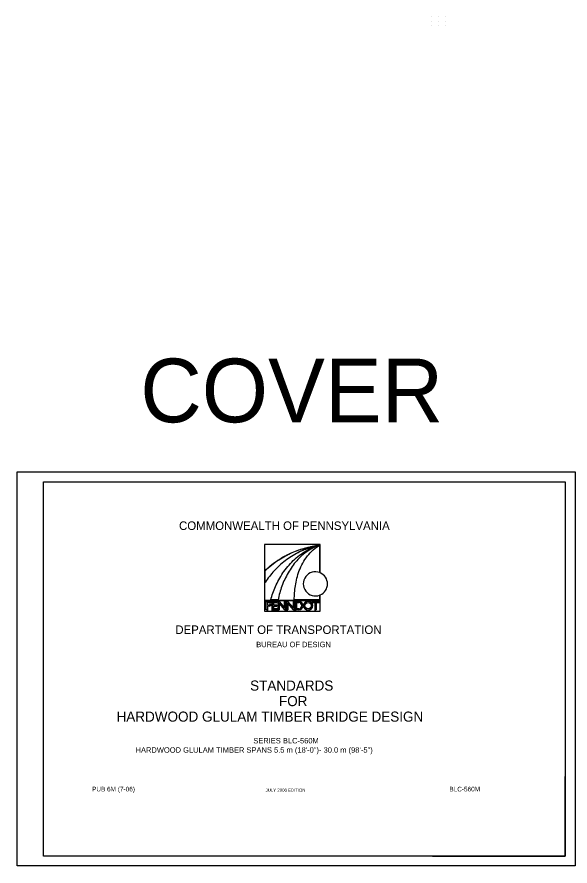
# Model space of a CAD drawing. Extents: x 637594 to 640253, y 297247 to 298527.
# Drawn here: x 637594 to 638428, y 297247 to 298527 of the extents above; entities that cross this region are included whole.
import ezdxf

# ---------------------------------------------------------------- set-up
doc = ezdxf.new("R2010")
doc.units = 0
for name, color, linetype in [('2', 7, 'Continuous'), ('4', 7, 'Continuous'), ('62', 7, 'Continuous'), ('9', 7, 'Continuous'), ('PLT-BNDY', 7, 'Continuous')]:
    doc.layers.add(name, color=color, linetype=linetype)

msp = doc.modelspace()

# ---------------------------------------------------------------- linework, layer by layer
at = {"layer": '2'}
for p, q in [((637634.5, 297262.5), (637634.5, 297826.5)), ((637634.5, 297826.5), (638420.5, 297826.5)), ((638420.5, 297826.5), (638420.5, 297262.5)), ((638420.5, 297262.5), (638420.5, 297382.5)), ((638420.5, 297262.5), (637634.5, 297262.5)), ((638220.5, 297262.5), (638420.5, 297262.5))]:
    msp.add_line(p, q, dxfattribs=at)
at = {"layer": '62'}
for p, q in [((638219.4, 298527.5), (638219.4, 298527.5)), ((638219.4, 298520.8), (638219.4, 298520.8)), ((638229.8, 298527.5), (638229.8, 298527.5)), ((638229.8, 298520.8), (638229.8, 298520.8)), ((638240.2, 298527.5), (638240.2, 298527.5)), ((638240.2, 298520.8), (638240.2, 298520.8)), ((638219.4, 298514.1), (638219.4, 298514.1)), ((638229.8, 298514.1), (638229.8, 298514.1)), ((638240.2, 298514.1), (638240.2, 298514.1))]:
    msp.add_line(p, q, dxfattribs=at)
at = {"layer": '9'}
for p, q in [((638051.6, 297732.1), (637967.3, 297732.1)), ((637967.3, 297732.1), (637967.3, 297647.9)), ((638051.6, 297732.1), (637967.3, 297732.1)), ((637967.3, 297732.1), (637967.3, 297674.9)), ((638051.6, 297732.1), (638050.6, 297731.1)), ((638050.6, 297731.1), (638051.6, 297732.1)), ((638051.6, 297732.1), (638050.6, 297731.1)), ((638050.6, 297731.1), (638050.6, 297689.8)), ((638050.6, 297731.1), (638050.6, 297689.8)), ((638051.6, 297689.4), (638051.6, 297732.1)), ((638051.6, 297689.4), (638051.6, 297732.1)), ((637967.3, 297674.9), (637968.3, 297674.9)), ((637967.3, 297674.9), (637968.3, 297674.9)), ((637968.3, 297674.9), (637967.3, 297674.9)), ((637967.3, 297674.9), (637967.3, 297647.9)), ((638051.6, 297647.9), (637967.3, 297647.9)), ((637967.3, 297647.9), (637967.3, 297631.9)), ((637974.3, 297647.9), (637967.3, 297647.9)), ((637967.3, 297647.9), (637967.3, 297631.9)), ((637967.3, 297647.9), (637976.9, 297647.9)), ((637970.1, 297633.7), (637970.1, 297646.4)), ((637970.1, 297646.4), (637974.3, 297646.4)), ((637970.1, 297633.7), (637970.1, 297646.4)), ((637970.1, 297646.4), (637974.3, 297646.4)), ((637974.3, 297647.9), (637974.3, 297646.4)), ((637974.3, 297646.4), (637974.3, 297647.9)), ((637986.3, 297647.9), (637974.3, 297647.9)), ((637974.3, 297647.9), (637974.3, 297646.4)), ((637976.9, 297647.9), (637976.9, 297648.9)), ((637976.9, 297647.9), (637976.9, 297648.9)), ((637976.9, 297648.9), (637976.9, 297647.9)), ((637976.9, 297647.9), (638012.4, 297647.9)), ((637979.3, 297646.4), (637979.3, 297633.7)), ((637986.3, 297646.4), (637979.3, 297646.4)), ((637979.3, 297633.7), (637979.3, 297646.4)), ((637979.3, 297646.4), (637986.3, 297646.4)), ((637986.3, 297647.9), (637986.3, 297646.4)), ((637986.3, 297646.4), (637986.3, 297647.9)), ((637999.5, 297647.9), (637986.3, 297647.9)), ((637986.3, 297647.9), (637986.3, 297646.4)), ((637986.3, 297644.7), (637986.3, 297646.4)), ((637986.3, 297646.4), (637986.3, 297644.7)), ((637989.5, 297646.4), (637988.1, 297646.4)), ((637988.1, 297646.4), (637988.1, 297633.7)), ((637988.1, 297633.7), (637988.1, 297646.4)), ((637988.1, 297646.4), (637989.5, 297646.4)), ((637997.8, 297636.6), (637989.5, 297646.4)), ((637989.5, 297646.4), (637997.8, 297636.6)), ((637999.5, 297646.4), (637997.8, 297646.4)), ((637997.8, 297646.4), (637997.8, 297636.6)), ((637997.8, 297636.6), (637997.8, 297646.4)), ((637997.8, 297646.4), (637999.5, 297646.4)), ((637999.5, 297647.9), (637999.5, 297646.4)), ((637999.5, 297646.4), (637999.5, 297647.9)), ((638012.7, 297647.9), (637999.5, 297647.9)), ((637999.5, 297647.9), (637999.5, 297646.4)), ((637999.5, 297633.7), (637999.5, 297646.4)), ((637999.5, 297646.4), (637999.5, 297633.7)), ((638002.7, 297646.4), (638001.2, 297646.4)), ((638001.2, 297646.4), (638001.2, 297633.7)), ((638001.2, 297633.7), (638001.2, 297646.4)), ((638001.2, 297646.4), (638002.7, 297646.4)), ((638011, 297636.6), (638002.7, 297646.4)), ((638002.7, 297646.4), (638011, 297636.6)), ((638012.7, 297646.4), (638011, 297646.4)), ((638011, 297646.4), (638011, 297636.6)), ((638011, 297636.6), (638011, 297646.4)), ((638011, 297646.4), (638012.7, 297646.4)), ((638050.6, 297648.9), (638012.4, 297648.9)), ((638012.4, 297647.9), (638012.4, 297648.9)), ((638012.4, 297647.9), (638012.4, 297648.9)), ((638050.6, 297648.9), (638012.4, 297648.9)), ((638012.4, 297648.9), (638012.4, 297647.9)), ((638012.4, 297647.9), (638051.6, 297647.9)), ((638012.7, 297647.9), (638012.7, 297646.4)), ((638012.7, 297646.4), (638012.7, 297647.9)), ((638019.4, 297647.9), (638012.7, 297647.9)), ((638012.7, 297647.9), (638012.7, 297646.4)), ((638012.7, 297633.7), (638012.7, 297646.4)), ((638012.7, 297646.4), (638012.7, 297633.7)), ((638014.4, 297633.7), (638014.4, 297646.4)), ((638014.4, 297646.4), (638019.4, 297646.4)), ((638014.4, 297633.7), (638014.4, 297646.4)), ((638014.4, 297646.4), (638019.4, 297646.4)), ((638014.4, 297633.7), (638014.4, 297646.4)), ((638014.4, 297646.4), (638019.4, 297646.4)), ((638019.4, 297647.9), (638019.4, 297646.4)), ((638019.4, 297646.4), (638019.4, 297647.9)), ((638033.3, 297647.9), (638019.4, 297647.9)), ((638019.4, 297647.9), (638019.4, 297646.4)), ((638033.3, 297647.9), (638033.3, 297646.6)), ((638033.3, 297646.6), (638033.3, 297647.9)), ((638050, 297647.9), (638033.3, 297647.9)), ((638033.3, 297647.9), (638033.3, 297646.6)), ((638050, 297646.4), (638039.6, 297646.4)), ((638039.6, 297646.4), (638039.6, 297644.7)), ((638050, 297646.4), (638039.6, 297646.4)), ((638039.6, 297646.4), (638050, 297646.4)), ((638039.6, 297644.7), (638039.6, 297646.4)), ((638039.6, 297646.4), (638050, 297646.4)), ((638050, 297647.9), (638050, 297646.4)), ((638050, 297646.4), (638050, 297647.9)), ((638051.6, 297647.9), (638050, 297647.9)), ((638050, 297647.9), (638050, 297646.4)), ((638050, 297644.7), (638050, 297646.4)), ((638050, 297646.4), (638050, 297644.7)), ((638050.6, 297655.7), (638050.6, 297648.9)), ((638050.6, 297655.7), (638050.6, 297648.9)), ((638051.6, 297647.9), (638051.6, 297656.1)), ((638051.6, 297647.9), (638051.6, 297656.1)), ((638051.6, 297631.9), (638051.6, 297647.9)), ((638051.6, 297631.9), (638051.6, 297647.9)), ((637972, 297633.7), (637970.1, 297633.7)), ((637972, 297633.7), (637970.1, 297633.7)), ((637974.3, 297644.7), (637972, 297644.7)), ((637972, 297644.7), (637972, 297640.8)), ((637972, 297640.8), (637974.3, 297640.8)), ((637974.3, 297639.2), (637972, 297639.2)), ((637972, 297639.2), (637972, 297633.7)), ((637974.3, 297639.2), (637972, 297639.2)), ((637972, 297639.2), (637972, 297633.7)), ((637972, 297631.9), (637972, 297633.7)), ((637972, 297631.9), (637972, 297633.7)), ((637972, 297633.7), (637972, 297631.9)), ((637979.3, 297633.7), (637986.4, 297633.7)), ((637979.3, 297631.9), (637979.3, 297633.7)), ((637979.3, 297631.9), (637979.3, 297633.7)), ((637986.4, 297633.7), (637979.3, 297633.7)), ((637979.3, 297633.7), (637979.3, 297631.9)), ((637981.1, 297640.8), (637981.1, 297644.7)), ((637981.1, 297644.7), (637986.3, 297644.7)), ((637986.3, 297644.7), (637981.1, 297644.7)), ((637981.1, 297644.7), (637981.1, 297640.8)), ((637986, 297640.8), (637981.1, 297640.8)), ((637981.1, 297640.8), (637986, 297640.8)), ((637981.1, 297635.4), (637981.1, 297639.2)), ((637981.1, 297639.2), (637986, 297639.2)), ((637986, 297639.2), (637981.1, 297639.2)), ((637981.1, 297639.2), (637981.1, 297635.4)), ((637986.4, 297635.4), (637981.1, 297635.4)), ((637981.1, 297635.4), (637986.4, 297635.4)), ((637986, 297639.2), (637986, 297640.8)), ((637986, 297640.8), (637986, 297639.2)), ((637986.4, 297633.7), (637986.4, 297635.4)), ((637986.4, 297635.4), (637986.4, 297633.7)), ((637988.1, 297633.7), (637989.7, 297633.7)), ((637988.1, 297631.9), (637988.1, 297633.7)), ((637988.1, 297631.9), (637988.1, 297633.7)), ((637989.7, 297633.7), (637988.1, 297633.7)), ((637988.1, 297633.7), (637988.1, 297631.9)), ((637989.7, 297633.7), (637989.7, 297643.5)), ((637989.7, 297643.5), (637998, 297633.7)), ((637998, 297633.7), (637989.7, 297643.5)), ((637989.7, 297643.5), (637989.7, 297633.7)), ((637998, 297633.7), (637999.5, 297633.7)), ((637999.5, 297633.7), (637998, 297633.7)), ((638001.2, 297633.7), (638002.9, 297633.7)), ((638001.2, 297631.9), (638001.2, 297633.7)), ((638001.2, 297631.9), (638001.2, 297633.7)), ((638002.9, 297633.7), (638001.2, 297633.7)), ((638001.2, 297633.7), (638001.2, 297631.9)), ((638002.9, 297633.7), (638002.9, 297643.6)), ((638002.9, 297643.6), (638011.2, 297633.7)), ((638011.2, 297633.7), (638002.9, 297643.6)), ((638002.9, 297643.6), (638002.9, 297633.7)), ((638011.2, 297633.7), (638012.7, 297633.7)), ((638012.7, 297633.7), (638011.2, 297633.7)), ((638019.4, 297633.7), (638014.4, 297633.7)), ((638019.4, 297633.7), (638014.4, 297633.7)), ((638014.4, 297631.9), (638014.4, 297633.7)), ((638014.4, 297631.9), (638014.4, 297633.7)), ((638019.4, 297633.7), (638014.4, 297633.7)), ((638014.4, 297633.7), (638014.4, 297631.9)), ((638016.2, 297635.4), (638016.2, 297644.7)), ((638016.2, 297644.7), (638019.2, 297644.7)), ((638019.2, 297635.4), (638016.2, 297635.4)), ((638033.3, 297631.9), (638033.3, 297633.4)), ((638033.3, 297631.9), (638033.3, 297633.4)), ((638033.3, 297633.4), (638033.3, 297631.9)), ((638039.6, 297644.7), (638043.8, 297644.7)), ((638043.8, 297644.7), (638039.6, 297644.7)), ((638043.8, 297644.7), (638043.8, 297633.7)), ((638043.8, 297633.7), (638043.8, 297644.7)), ((638043.8, 297633.7), (638045.6, 297633.7)), ((638043.8, 297631.9), (638043.8, 297633.7)), ((638043.8, 297631.9), (638043.8, 297633.7)), ((638045.6, 297633.7), (638043.8, 297633.7)), ((638043.8, 297633.7), (638043.8, 297631.9)), ((638045.6, 297633.7), (638045.6, 297644.7)), ((638045.6, 297644.7), (638050, 297644.7)), ((638050, 297644.7), (638045.6, 297644.7)), ((638045.6, 297644.7), (638045.6, 297633.7)), ((637967.3, 297631.9), (638051.6, 297631.9)), ((637967.3, 297631.9), (637972, 297631.9)), ((637972, 297631.9), (637979.3, 297631.9)), ((637979.3, 297631.9), (637988.1, 297631.9)), ((637988.1, 297631.9), (638001.2, 297631.9)), ((638001.2, 297631.9), (638014.4, 297631.9)), ((638014.4, 297631.9), (638033.3, 297631.9)), ((638033.3, 297631.9), (638043.8, 297631.9)), ((638043.8, 297631.9), (638051.6, 297631.9))]:
    msp.add_line(p, q, dxfattribs=at)
for points in [[(637968.3, 297674.9), (637968.3, 297692.5)], [(637968.3, 297674.9), (637968.3, 297692.5)], [(637988.3, 297648.9), (637976.9, 297648.9)], [(637988.3, 297648.9), (637976.9, 297648.9)]]:
    msp.add_lwpolyline(points, dxfattribs=at)
for radius in [6.61, 4.77]:
    msp.add_circle((638033.3, 297640), radius, dxfattribs=at)
for centre, radius, start, end in [((638044.2, 297672.8), 18.2, 69.389, 290.611), ((638044.2, 297672.8), 18.2, 69.389, 290.611), ((638044.2, 297672.8), 18.2, 294.0096, 65.9904), ((638044.2, 297672.8), 18.2, 294.0096, 65.9904), ((637974.3, 297642.8), 3.59, 270, 90), ((637974.3, 297642.8), 3.59, 270, 90), ((638019.4, 297640), 6.34, 270, 90), ((638019.4, 297640), 6.34, 270, 90), ((638019.4, 297640), 6.34, 270, 90), ((638033.3, 297640), 6.61, 90, 270), ((638033.3, 297640), 6.61, 270, 90), ((637974.3, 297642.7), 1.92, 270, 90), ((638019.2, 297640), 4.65, 270, 90)]:
    msp.add_arc(centre, radius, start, end, dxfattribs=at)
for points, degree in [([(638050.6, 297731.1), (638047.8, 297731.2), (638036.4, 297727.9), (638018.4, 297720.6), (637998.2, 297708.3), (637981.6, 297692.9), (637972.4, 297681.1), (637968.3, 297674.9)], 3), ([(637968.3, 297692.5), (637974.7, 297698.8), (637987.7, 297709.3), (638009.1, 297720.8), (638030.4, 297727.6), (638044.6, 297730.9), (638050.6, 297731.1)], 3), ([(638048.6, 297731), (638046.1, 297730.7), (638035.6, 297727.6), (638018.4, 297720.6), (637998.2, 297708.3), (637981.6, 297692.9), (637972.4, 297681.1), (637968.3, 297674.9)], 3), ([(637976.9, 297648.9), (637978.7, 297655.3), (637983.5, 297668.5), (637994.3, 297689.6), (638010.2, 297708.5), (638030.1, 297723.7), (638044, 297729.8), (638050.6, 297731.1)], 3), ([(637976.9, 297648.9), (637978.7, 297655.3), (637983.5, 297668.5), (637994.3, 297689.6), (638010.2, 297708.5), (638030.1, 297723.7), (638044, 297729.8), (638050.6, 297731.1)], 3), ([(638050.6, 297731.1), (638045, 297729.6), (638032.2, 297722.9), (638015.3, 297708.4), (638002.7, 297689.6), (637993, 297669.8), (637989.4, 297655.7), (637988.3, 297648.9)], 3), ([(638050.6, 297731.1), (638045, 297729.6), (638032.2, 297722.9), (638015.3, 297708.4), (638002.7, 297689.6), (637993, 297669.8), (637989.4, 297655.7), (637988.3, 297648.9)], 3), ([(637989, 297709.2), (637995.5, 297713.5), (638009.1, 297720.8), (638029.7, 297727.4), (638043.1, 297730.5), (638048.6, 297731)], 3), ([(638012.4, 297648.9), (638012.4, 297655.9), (638013.6, 297669.6), (638018.8, 297692.9), (638030.7, 297715.7), (638044.4, 297727.5), (638050.6, 297731.1)], 3), ([(638012.4, 297648.9), (638012.4, 297655.9), (638013.6, 297669.6), (638018.8, 297692.9), (638030.7, 297715.7), (638044.4, 297727.5), (638050.6, 297731.1)], 3), ([(638048.6, 297731), (638049.3, 297731.1), (638049.9, 297731.1), (638050.6, 297731.1)], 2), ([(638050.6, 297731.1), (638049.9, 297731.1), (638049.2, 297731.1), (638048.6, 297731)], 2), ([(637968.3, 297692.5), (637974.7, 297698.8), (637981.6, 297704.4), (637989, 297709.2)], 2)]:
    msp.add_open_spline(points, degree=degree, dxfattribs=at)
at = {"layer": 'PLT-BNDY'}
msp.add_lwpolyline([(637594.5, 297841.5), (638435.5, 297841.5), (638435.5, 297247.5), (637594.5, 297247.5)], close=True, dxfattribs=at)

# ---------------------------------------------------------------- texts
at = {"layer": '4'}
for s, height, p in [('COVER', 96, (637780.3, 297916.4)), ('BUREAU OF DESIGN', 8.191, (637955, 297577.4)), ('STANDARDS', 15.21, (637945.8, 297511.9)), ('FOR', 15.21, (637989.3, 297488.5)), ('HARDWOOD GLULAM TIMBER BRIDGE DESIGN', 15.212, (637744.5, 297465.1)), ('HARDWOOD GLULAM TIMBER SPANS 5.5 m (18\'-0")- 30.0 m (98\'-5")', 8.191, (637773.2, 297418.3)), ('PUB 6M (7-06)', 7.021, (637707.6, 297359.9)), ('BLC-560M', 7.02, (638246.1, 297359.9))]:
    msp.add_text(s, height=height, dxfattribs=at).set_placement(p)
for s, height, p in [('COMMONWEALTH OF PENNSYLVANIA', 12.872, (637838.7, 297754.1)), ('DEPARTMENT OF TRANSPORTATION', 12.872, (637833.1, 297597.3)), ('SERIES BLC-560M', 8.191, (637950.6, 297432.3)), ('JULY 2006 EDITION', 4.681, (637969.2, 297359.5))]:
    msp.add_text(s, height=height, rotation=360, dxfattribs=at).set_placement(p)

doc.saveas('drawing.dxf')
